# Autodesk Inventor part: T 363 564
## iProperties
Created: 2006-04
Part Number: T 363 564
Material: 1.0330.03
Document SubType Name: Sheet Metal
Designer: I.Baliuc
Description: Abdeckung, rechts - links
Density: 7.84 g/cm^3
Sheet Metal Rule: Default
Title: Abdeckung, rechts - links
Company: Mayer & Müller AG Schaltgeräte
HalbzeugNorm: DIN 1541
Zweck: LBK DC-Schalter
Abmessung: St.Bl. 3mm
Author: T.Messerschmitt
Keywords: 266493
Revision Number: 363564
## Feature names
1. Bohrung1 [Hole]
2. Grobblech1
3. Grobblech2
4. Biegung1
